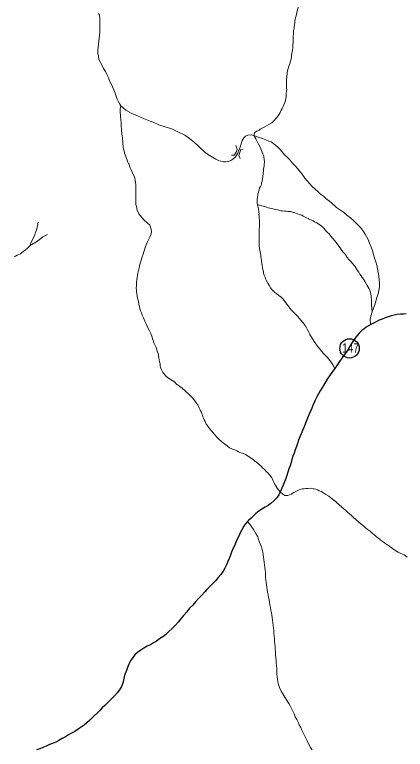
# Model space of a CAD drawing. Extents: x 781.9 to 808.1, y 7453.3 to 7481.5.
# Drawn here: x 788.63 to 791.98, y 7466.86 to 7473.15 of the extents above; entities that cross this region are included whole.
import ezdxf
from ezdxf.enums import TextEntityAlignment as Align

# ---------------------------------------------------------------- set-up
doc = ezdxf.new("R2010")
doc.units = 0
doc.header["$LTSCALE"] = 0.032
doc.linetypes.add('LONG_DASHED', pattern=[7.5, 6, -1.5])
doc.linetypes.add('MEDIUM_DASHED', pattern=[4.5, 3, -1.5])
for name, color, linetype, lineweight in [('11', 7, 'Continuous', 13), ('13', 7, 'Continuous', 25), ('4', 7, 'LONG_DASHED', 25), ('5', 7, 'LONG_DASHED', 13), ('6', 7, 'MEDIUM_DASHED', 13)]:
    doc.layers.add(name, color=color, linetype=linetype, lineweight=lineweight)
doc.layers.add('61', color=7, linetype='Continuous')

msp = doc.modelspace()

# ---------------------------------------------------------------- linework, layer by layer
at = {"layer": '11'}
for points in [[(790.5284, 7472.0312), (790.54, 7472.0008), (790.5313, 7471.9734), (790.5226, 7471.9588), (790.5132, 7471.9479), (790.4915, 7471.9494)], [(790.5636, 7471.9208), (790.5517, 7471.9443), (790.5691, 7471.9964), (790.5905, 7471.9997)]]:
    msp.add_lwpolyline(points, dxfattribs=at)
at = {"layer": '13'}
msp.add_circle((791.5019, 7470.2932), 0.083, dxfattribs=at)
msp.add_circle((791.5019, 7470.2932), 0.083, dxfattribs=at)
msp.add_circle((791.5019, 7470.2932), 0.083, dxfattribs=at)
at = {"layer": '4'}
for points in [[(791.9875, 7470.5881), (791.9632, 7470.5864), (791.9372, 7470.5848), (791.9113, 7470.5824), (791.8853, 7470.5783), (791.8594, 7470.571), (791.8334, 7470.5637), (791.8075, 7470.554), (791.7815, 7470.5443), (791.7556, 7470.5337), (791.7297, 7470.5199), (791.7025, 7470.5055), (791.6849, 7470.4975)], [(791.6849, 7470.4975), (791.6441, 7470.4735), (791.6233, 7470.4591), (791.6085, 7470.4473), (791.5845, 7470.4233), (791.5565, 7470.3897), (791.5197, 7470.3345), (791.4805, 7470.2729)], [(791.4805, 7470.2729), (791.4421, 7470.2185), (791.4045, 7470.1641), (791.3765, 7470.1217)], [(791.3765, 7470.1217), (791.3557, 7470.0945), (791.3109, 7470.0289), (791.2773, 7469.9753)], [(791.2773, 7469.9753), (791.2489, 7469.9281), (791.2351, 7469.9038), (791.2237, 7469.8835), (791.2107, 7469.8559), (791.1978, 7469.83), (791.1872, 7469.8033), (791.1775, 7469.7822), (791.1702, 7469.7611), (791.1566, 7469.7291), (791.1422, 7469.6947), (791.1254, 7469.6531), (791.1118, 7469.6203), (791.0981, 7469.5892), (791.0883, 7469.5616), (791.0762, 7469.5341), (791.0656, 7469.5065), (791.0551, 7469.4789), (791.0462, 7469.4514), (791.0364, 7469.4237), (791.0267, 7469.3962), (791.017, 7469.3687), (791.008, 7469.3411), (791.0008, 7469.3152), (790.9918, 7469.2876), (790.9829, 7469.26), (790.974, 7469.2325), (790.9643, 7469.2049), (790.9545, 7469.1773), (790.944, 7469.1498), (790.9327, 7469.1222), (790.9213, 7469.0946), (790.91, 7469.0671), (790.9081, 7469.0635)], [(790.9081, 7469.0635), (790.8954, 7469.0395), (790.8775, 7469.0119), (790.8556, 7468.9892), (790.8264, 7468.9657), (790.8037, 7468.9463), (790.7778, 7468.9325), (790.7503, 7468.9154), (790.7235, 7468.8984), (790.6999, 7468.879), (790.6781, 7468.8595), (790.6578, 7468.8401), (790.6362, 7468.8193), (790.6266, 7468.8089)], [(790.6266, 7468.8089), (790.6106, 7468.7897), (790.5954, 7468.7697), (790.5792, 7468.7395), (790.5654, 7468.7136), (790.5524, 7468.686), (790.5394, 7468.6586), (790.5273, 7468.6309), (790.5151, 7468.6033), (790.5022, 7468.5758), (790.4908, 7468.5482), (790.4803, 7468.5206), (790.4697, 7468.4931), (790.46, 7468.4671), (790.447, 7468.4395), (790.4332, 7468.412), (790.4186, 7468.3844), (790.3984, 7468.3569), (790.3773, 7468.3309), (790.3521, 7468.3025), (790.3254, 7468.2741), (790.2978, 7468.2474), (790.2792, 7468.2287), (790.2614, 7468.2076), (790.2354, 7468.1801), (790.2087, 7468.1501), (790.1827, 7468.1209), (790.1576, 7468.0933), (790.1316, 7468.0666), (790.1065, 7468.0366), (790.0797, 7468.0066), (790.0546, 7467.9742), (790.0335, 7467.9474), (790.0084, 7467.9198), (789.9857, 7467.8955), (789.9484, 7467.8615), (789.9265, 7467.8428), (789.9006, 7467.8217), (789.8746, 7467.8047), (789.8479, 7467.7852), (789.8211, 7467.7707), (789.7952, 7467.7552), (789.7676, 7467.7415), (789.74, 7467.726), (789.7125, 7467.709), (789.6849, 7467.6896), (789.6622, 7467.6677), (789.6443, 7467.6458), (789.6249, 7467.6158), (789.6119, 7467.5882)], [(789.6119, 7467.5882), (789.5998, 7467.5607), (789.59, 7467.5331), (789.5803, 7467.5072), (789.5714, 7467.4796), (789.5649, 7467.452), (789.5584, 7467.4245)], [(789.5584, 7467.4245), (789.5471, 7467.3969), (789.5308, 7467.3693), (789.5106, 7467.3418), (789.4887, 7467.3174), (789.4587, 7467.2883), (789.4319, 7467.2599), (789.4043, 7467.2339), (789.3825, 7467.2137), (789.3614, 7467.1918), (789.3419, 7467.1707), (789.3144, 7467.1463), (789.2957, 7467.1285), (789.2738, 7467.1066), (789.252, 7467.0863), (789.2268, 7467.0661), (789.2025, 7467.0474), (789.1758, 7467.0304), (789.1482, 7467.0126), (789.1206, 7466.998), (789.0931, 7466.9826), (789.0671, 7466.9672), (789.0395, 7466.951), (789.012, 7466.9355), (788.9844, 7466.921), (788.9568, 7466.9096), (788.9293, 7466.8991), (788.9017, 7466.8861), (788.8741, 7466.8747), (788.8466, 7466.8642), (788.819, 7466.8545)]]:
    msp.add_lwpolyline(points, dxfattribs=at)
at = {"layer": '5'}
for points in [[(789.3515, 7473.1611), (789.358, 7473.1475), (789.3612, 7473.1259), (789.362, 7473.0843), (789.363, 7473.0779), (789.3622, 7473.0544), (789.3614, 7473.0285), (789.3606, 7473.0025), (789.3582, 7472.9766), (789.3549, 7472.9506), (789.3525, 7472.9247), (789.35, 7472.8987), (789.3484, 7472.8728), (789.346, 7472.8469), (789.3452, 7472.8209), (789.35, 7472.795), (789.3541, 7472.7674), (789.3664, 7472.7415), (789.3809, 7472.7155), (789.3946, 7472.6896), (789.4108, 7472.6636), (789.4214, 7472.6377), (789.4352, 7472.6117), (789.4457, 7472.5858), (789.4587, 7472.5598), (789.4709, 7472.5323), (789.4822, 7472.5063), (789.4927, 7472.4804), (789.5016, 7472.4544), (789.5114, 7472.4285), (789.5227, 7472.4061), (789.5331, 7472.3845), (789.5419, 7472.3709)], [(789.5419, 7472.3709), (789.586, 7472.3341), (789.6301, 7472.3069), (789.6846, 7472.2853), (789.7375, 7472.2621), (789.766, 7472.2501), (789.7919, 7472.2396), (789.8179, 7472.2298), (789.8684, 7472.2074), (789.9301, 7472.189), (789.9589, 7472.1796), (789.9849, 7472.1699), (789.997, 7472.1658), (790.0315, 7472.1474), (790.0903, 7472.1188), (790.1179, 7472.0993), (790.1438, 7472.079), (790.173, 7472.0563), (790.2005, 7472.032), (790.2202, 7472.0124), (790.2675, 7471.9684), (790.2978, 7471.9477), (790.3562, 7471.9145), (790.3789, 7471.9023), (790.4, 7471.8966)], [(790.5183, 7471.9282), (790.5297, 7471.9429), (790.5435, 7471.9647), (790.5516, 7471.9858), (790.5524, 7471.9882), (790.5653, 7472.0162), (790.5816, 7472.075), (790.5953, 7472.0958), (790.6105, 7472.111), (790.6297, 7472.1198), (790.6578, 7472.1214), (790.6826, 7472.1158)], [(790.6826, 7472.1158), (790.7195, 7472.103), (790.7547, 7472.091), (790.7843, 7472.0806), (790.8102, 7472.0693), (790.8305, 7472.0612), (790.853, 7472.0452), (790.8874, 7472.018), (790.9107, 7471.9924), (790.9451, 7471.9516), (790.9683, 7471.9307), (790.9943, 7471.9048), (791.0105, 7471.8836), (791.038, 7471.8529), (791.0567, 7471.8342), (791.0786, 7471.8058), (791.0956, 7471.7839), (791.1199, 7471.7523), (791.137, 7471.732), (791.1621, 7471.7037), (791.1783, 7471.6834), (791.2067, 7471.6582), (791.2302, 7471.638), (791.2529, 7471.6153), (791.2772, 7471.5974), (791.2999, 7471.578), (791.3226, 7471.5594), (791.3429, 7471.544), (791.3902, 7471.5008), (791.4491, 7471.4588), (791.4791, 7471.4345), (791.5091, 7471.4102), (791.5391, 7471.3858), (791.5675, 7471.3582), (791.5956, 7471.3279), (791.6204, 7471.2943), (791.6365, 7471.2703), (791.6597, 7471.2319), (791.6718, 7471.1935), (791.6858, 7471.1588), (791.6972, 7471.128), (791.7069, 7471.0972), (791.7167, 7471.0664), (791.7264, 7471.0356), (791.7353, 7471.0048), (791.7418, 7470.974), (791.7483, 7470.9432), (791.7531, 7470.9124), (791.7564, 7470.8816), (791.7572, 7470.8508), (791.7572, 7470.82), (791.7539, 7470.7891), (791.7459, 7470.76), (791.7369, 7470.7291), (791.728, 7470.6983), (791.7183, 7470.6675), (791.7077, 7470.6383), (791.6964, 7470.6075)], [(790.4, 7471.8966), (790.4211, 7471.8918), (790.4422, 7471.8902), (790.4632, 7471.8942), (790.4843, 7471.9023), (790.5029, 7471.9145), (790.5183, 7471.9282)], [(791.6964, 7470.6075), (791.6859, 7470.5767), (791.6794, 7470.5459), (791.6786, 7470.5251), (791.6849, 7470.4975)], [(790.6266, 7468.8089), (790.6434, 7468.7911), (790.6594, 7468.7695), (790.6797, 7468.742), (790.691, 7468.7217), (790.7016, 7468.7006), (790.7147, 7468.6779), (790.7227, 7468.6552), (790.7308, 7468.6341), (790.7389, 7468.6131), (790.7462, 7468.592), (790.7519, 7468.5709), (790.7592, 7468.5482), (790.7616, 7468.5255), (790.7648, 7468.5044), (790.7673, 7468.4833), (790.7705, 7468.4622), (790.7721, 7468.4396), (790.7754, 7468.4168), (790.7778, 7468.3958), (790.7802, 7468.3747), (790.7819, 7468.3536), (790.7827, 7468.3325), (790.7859, 7468.3098), (790.7883, 7468.2887), (790.79, 7468.2677), (790.7924, 7468.2466), (790.7948, 7468.2255), (790.7997, 7468.2044), (790.8046, 7468.1817), (790.8078, 7468.1606), (790.8119, 7468.1396), (790.8167, 7468.1185), (790.8191, 7468.0974), (790.824, 7468.0747), (790.8281, 7468.052), (790.8322, 7468.0279), (790.8394, 7467.9879), (790.8419, 7467.9661), (790.8435, 7467.9434), (790.8467, 7467.9207), (790.8492, 7467.898), (790.8516, 7467.8736), (790.854, 7467.8509), (790.8564, 7467.8282), (790.8581, 7467.8055), (790.8597, 7467.7828), (790.8621, 7467.7585), (790.8646, 7467.7358), (790.8654, 7467.7131), (790.867, 7467.6904), (790.8686, 7467.6677), (790.8702, 7467.6434), (790.8719, 7467.6191), (790.8727, 7467.5964), (790.8751, 7467.5737), (790.8775, 7467.551), (790.8783, 7467.5266), (790.8791, 7467.5039), (790.8808, 7467.4812), (790.8832, 7467.4585), (790.8873, 7467.4358), (790.8929, 7467.4131), (790.9017, 7467.3888), (790.9172, 7467.3572), (790.931, 7467.3353), (790.9481, 7467.3061), (790.9626, 7467.2834), (790.9813, 7467.2526), (790.9943, 7467.2315), (791.0048, 7467.2088), (791.0162, 7467.1861), (791.0283, 7467.1618), (791.0372, 7467.1375), (791.0494, 7467.1148), (791.0608, 7467.0921), (791.0713, 7467.0694), (791.0835, 7467.045), (791.0932, 7467.0223), (791.1037, 7466.9996), (791.1159, 7466.9769), (791.1264, 7466.9542), (791.1386, 7466.9315), (791.1507, 7466.9072), (791.1686, 7466.8756), (791.1824, 7466.8537)]]:
    msp.add_lwpolyline(points, dxfattribs=at)
at = {"layer": '6'}
for points in [[(791.0665, 7473.2336), (791.0583, 7473.2052), (791.0534, 7473.1841), (791.0494, 7473.1695), (791.0461, 7473.1549), (791.0437, 7473.1404), (791.0388, 7473.1258)], [(791.0388, 7473.1258), (791.0372, 7473.1112), (791.034, 7473.0966), (791.0324, 7473.082), (791.0308, 7473.0682), (791.0267, 7473.035), (791.0226, 7473.0123), (791.0226, 7472.9977), (791.0202, 7472.9831), (791.0194, 7472.9685), (791.0194, 7472.9539), (791.0186, 7472.9393), (791.0178, 7472.9247), (791.0178, 7472.9101), (791.017, 7472.8963), (791.0145, 7472.8712), (791.0121, 7472.8485), (791.0097, 7472.8339), (791.0072, 7472.8193), (791.0056, 7472.8047), (791.0032, 7472.7901), (791.0007, 7472.7755), (790.9975, 7472.7609), (790.9941, 7472.7463), (790.9919, 7472.739), (790.9821, 7472.7107), (790.9756, 7472.6904), (790.9699, 7472.6717), (790.9683, 7472.6571), (790.9659, 7472.6425), (790.9643, 7472.628), (790.9634, 7472.6134), (790.9626, 7472.5988), (790.9627, 7472.5931), (790.961, 7472.5631), (790.9626, 7472.5404), (790.9626, 7472.5258), (790.9634, 7472.5112), (790.961, 7472.495), (790.9594, 7472.4804), (790.9594, 7472.4658), (790.9594, 7472.4496), (790.9594, 7472.4488), (790.9529, 7472.4204), (790.9464, 7472.3985), (790.9399, 7472.3782), (790.9326, 7472.3636), (790.9245, 7472.349), (790.9164, 7472.3328), (790.9091, 7472.3182), (790.9059, 7472.3126), (790.8897, 7472.2842), (790.8726, 7472.2639), (790.8597, 7472.2485), (790.8368, 7472.2264), (790.8103, 7472.2112), (790.7698, 7472.1883), (790.747, 7472.1755), (790.7373, 7472.1698), (790.7275, 7472.1633), (790.7178, 7472.1593), (790.7065, 7472.1536), (790.6967, 7472.1463), (790.6886, 7472.1391), (790.6886, 7472.1358), (790.6826, 7472.1158)], [(789.5419, 7472.3709), (789.5368, 7472.3455), (789.536, 7472.3198), (789.538, 7472.2849), (789.5389, 7472.2761), (789.5406, 7472.2534), (789.5438, 7472.2249), (789.5438, 7472.2193), (789.5454, 7472.2047), (789.5454, 7472.1901), (789.5478, 7472.1739), (789.5478, 7472.1577), (789.5503, 7472.1415), (789.5519, 7472.1269), (789.5535, 7472.1123), (789.5558, 7472.0956), (789.5602, 7472.0559), (789.5618, 7472.0102), (789.5694, 7471.9865), (789.5738, 7471.9647), (789.5835, 7471.9356), (789.5973, 7471.9039), (789.603, 7471.8885), (789.607, 7471.8772), (789.6127, 7471.8707), (789.616, 7471.8529), (789.6249, 7471.835), (789.6322, 7471.8172), (789.6452, 7471.7888), (789.6607, 7471.7564), (789.6614, 7471.7507), (789.6646, 7471.7329), (789.667, 7471.715), (789.6695, 7471.6972), (789.6703, 7471.6777), (789.6703, 7471.6583), (789.6695, 7471.6307), (789.6703, 7471.5958), (789.6695, 7471.5821), (789.6703, 7471.5626), (789.6695, 7471.5432), (789.6719, 7471.5253), (789.6768, 7471.5075), (789.6824, 7471.4783), (789.6954, 7471.445), (789.7076, 7471.4304), (789.7238, 7471.4101), (789.7417, 7471.3915), (789.7668, 7471.368), (789.7895, 7471.3477), (789.796, 7471.3324), (789.8032, 7471.3129), (789.804, 7471.2934), (789.8024, 7471.274), (789.7911, 7471.2448), (789.7757, 7471.2164), (789.7684, 7471.1993), (789.7603, 7471.1799), (789.7514, 7471.1564), (789.7416, 7471.1297), (789.7295, 7471.0915), (789.7278, 7471.0859), (789.723, 7471.068), (789.7165, 7471.0486), (789.7116, 7471.0291), (789.706, 7471.0113), (789.6986, 7470.9821), (789.6898, 7470.9489), (789.6873, 7470.9367), (789.6849, 7470.9172), (789.6808, 7470.8994), (789.6784, 7470.8816), (789.6759, 7470.8637), (789.6751, 7470.8345), (789.6744, 7470.8029), (789.6751, 7470.7972), (789.6768, 7470.7794), (789.68, 7470.7616), (789.6833, 7470.7437), (789.6849, 7470.7243), (789.6938, 7470.6951), (789.6971, 7470.6683), (789.7011, 7470.6513), (789.7043, 7470.6335), (789.71, 7470.6156), (789.7181, 7470.5962), (789.7254, 7470.5767), (789.7368, 7470.5556), (789.7481, 7470.5273), (789.7514, 7470.52), (789.7587, 7470.5021), (789.7684, 7470.4827), (789.7765, 7470.4632), (789.7862, 7470.4429), (789.7984, 7470.4194)], [(790.6826, 7472.1158), (790.6986, 7472.0873), (790.7195, 7472.048), (790.7351, 7472.0171), (790.7544, 7471.973), (790.766, 7471.9389), (790.7709, 7471.9052), (790.7713, 7471.904), (790.7729, 7471.8958), (790.7721, 7471.8885), (790.7705, 7471.8723), (790.7689, 7471.8561), (790.7681, 7471.8415), (790.7656, 7471.8269), (790.7648, 7471.8123), (790.7624, 7471.7976), (790.7616, 7471.7937), (790.7575, 7471.7621), (790.7551, 7471.7394), (790.7535, 7471.7248), (790.7486, 7471.7102), (790.7462, 7471.6956), (790.7381, 7471.681), (790.7316, 7471.6664), (790.7275, 7471.6518), (790.7243, 7471.6429), (790.717, 7471.608), (790.7137, 7471.5853), (790.7105, 7471.5707), (790.7097, 7471.5561)], [(790.7097, 7471.5561), (790.7101, 7471.5405), (790.7141, 7471.526)], [(790.7141, 7471.526), (790.7221, 7471.4867), (790.7265, 7471.4422), (790.7259, 7471.441), (790.7267, 7471.4248)], [(790.7141, 7471.526), (790.7315, 7471.5207), (790.7624, 7471.5107), (790.773, 7471.5074), (790.7892, 7471.5026), (790.8054, 7471.4977), (790.82, 7471.4953), (790.8347, 7471.492), (790.8573, 7471.4864), (790.8856, 7471.4799), (790.8962, 7471.4774), (790.9124, 7471.4726), (790.9286, 7471.4701), (790.9432, 7471.4685), (790.9578, 7471.4677), (790.9724, 7471.4669), (790.9951, 7471.4653), (791.0202, 7471.4572), (791.0259, 7471.4556), (791.0421, 7471.4499), (791.0567, 7471.4458), (791.0713, 7471.441), (791.0916, 7471.4329), (791.1054, 7471.4264), (791.1281, 7471.415), (791.1516, 7471.4021), (791.154, 7471.4012), (791.1702, 7471.3948), (791.1897, 7471.3842), (791.2027, 7471.3761), (791.2205, 7471.3672), (791.2318, 7471.3591), (791.2545, 7471.3445), (791.2748, 7471.3299), (791.2845, 7471.3193), (791.2967, 7471.304), (791.3137, 7471.2861), (791.3259, 7471.274), (791.3405, 7471.2545), (791.3583, 7471.2334), (791.3753, 7471.2132), (791.3842, 7471.2034), (791.3956, 7471.1897), (791.4086, 7471.1694), (791.4207, 7471.1556), (791.4305, 7471.141), (791.445, 7471.1199), (791.4686, 7471.0932), (791.471, 7471.0891), (791.4807, 7471.0729), (791.4969, 7471.0534), (791.514, 7471.0364), (791.5302, 7471.0186), (791.5464, 7470.9959), (791.561, 7470.9748), (791.5707, 7470.9602), (791.5813, 7470.9447), (791.5894, 7470.9302), (791.6007, 7470.9156), (791.6113, 7470.901), (791.621, 7470.8864), (791.6348, 7470.8629), (791.651, 7470.8386), (791.6542, 7470.8329), (791.6623, 7470.8167), (791.6688, 7470.8021), (791.6753, 7470.7931), (791.6769, 7470.7875), (791.681, 7470.7729), (791.6834, 7470.7583), (791.6858, 7470.7421), (791.6875, 7470.7259), (791.6898, 7470.7156), (791.691, 7470.6871), (791.691, 7470.6655), (791.6922, 7470.6354), (791.6964, 7470.6075)], [(790.7267, 7471.4248), (790.7283, 7471.4086), (790.7299, 7471.3923), (790.7316, 7471.3778), (790.7299, 7471.3632), (790.7299, 7471.3486), (790.7292, 7471.338), (790.7283, 7471.308), (790.7275, 7471.2837), (790.7275, 7471.2675), (790.7267, 7471.2529), (790.7267, 7471.2383), (790.7267, 7471.2237), (790.7275, 7471.2091), (790.7276, 7471.2067), (790.7283, 7471.1734), (790.7316, 7471.1491), (790.7341, 7471.1345), (790.7356, 7471.1199), (790.7389, 7471.1053), (790.7405, 7471.0907), (790.7429, 7471.0762), (790.7445, 7471.0616), (790.7478, 7471.0453), (790.7486, 7471.0364), (790.7535, 7471.0048), (790.7567, 7470.9821), (790.7599, 7470.9675), (790.7632, 7470.9529), (790.7656, 7470.9367), (790.7713, 7470.9205), (790.7778, 7470.9043), (790.7826, 7470.8897), (790.7875, 7470.8775), (790.8021, 7470.8515), (790.8151, 7470.8281), (790.8248, 7470.8118), (790.8353, 7470.7988), (790.8516, 7470.781), (790.8621, 7470.7713), (790.8792, 7470.7607), (790.897, 7470.747), (790.9172, 7470.7324), (790.9254, 7470.7235), (790.9343, 7470.7137), (790.9481, 7470.6951), (790.9578, 7470.6805), (790.974, 7470.661), (790.9837, 7470.6472), (790.9878, 7470.6408), (791.0072, 7470.6188), (791.0259, 7470.5978), (791.0445, 7470.5807), (791.0575, 7470.5661), (791.0721, 7470.5492), (791.0818, 7470.5378), (791.1037, 7470.511), (791.1207, 7470.4883), (791.1337, 7470.4681), (791.1426, 7470.4527), (791.1516, 7470.4324), (791.1613, 7470.4162), (791.1629, 7470.4121), (791.1767, 7470.3886), (791.1897, 7470.3658), (791.1994, 7470.3529), (791.2124, 7470.3335), (791.2221, 7470.3197), (791.2367, 7470.3011), (791.2432, 7470.2921), (791.2626, 7470.2702), (791.2797, 7470.2492), (791.2975, 7470.2305), (791.3145, 7470.2111), (791.3307, 7470.1908), (791.3348, 7470.1851), (791.3593, 7470.1526), (791.3765, 7470.1217)], [(788.8343, 7471.3751), (788.8283, 7471.3434), (788.8255, 7471.3307), (788.8214, 7471.3161), (788.8157, 7471.2999), (788.8101, 7471.2837), (788.8076, 7471.2764), (788.806, 7471.2723), (788.8044, 7471.2683), (788.8038, 7471.267), (788.7938, 7471.2409), (788.7721, 7471.196), (788.7641, 7471.1736)], [(788.7641, 7471.1736), (788.8272, 7471.2124), (788.8727, 7471.2473), (788.9133, 7471.2697)], [(788.7641, 7471.1736), (788.7428, 7471.1514), (788.7233, 7471.1345), (788.6982, 7471.1159), (788.6941, 7471.1134), (788.6812, 7471.1037), (788.6682, 7471.0972), (788.6544, 7471.0907), (788.6405, 7471.0842), (788.6277, 7471.0802)], [(789.7984, 7470.4194), (789.8098, 7470.3894), (789.8146, 7470.374), (789.8219, 7470.3546), (789.8276, 7470.3351), (789.8357, 7470.3173), (789.8446, 7470.2994)], [(789.8446, 7470.2994), (789.8535, 7470.2703), (789.8649, 7470.2402), (789.8649, 7470.233), (789.8673, 7470.2135), (789.8697, 7470.1957), (789.873, 7470.1778), (789.8786, 7470.16), (789.8803, 7470.1422), (789.8876, 7470.1146), (789.9014, 7470.0854), (789.9119, 7470.074), (789.9281, 7470.0554), (789.9354, 7470.0489), (789.946, 7470.0408), (789.9467, 7470.0409), (789.968, 7470.0253), (790.0017, 7470.0053), (790.023, 7469.984), (790.0287, 7469.98), (790.0408, 7469.9735), (790.0514, 7469.9637), (790.0635, 7469.954), (790.0765, 7469.9451), (790.0878, 7469.9354), (790.1024, 7469.9201), (790.126, 7469.9013), (790.1308, 7469.8956), (790.1413, 7469.8835), (790.1559, 7469.8697), (790.1689, 7469.8551), (790.177, 7469.8438), (790.1867, 7469.8276), (790.2005, 7469.8089), (790.2135, 7469.7846), (790.2192, 7469.7724), (790.2257, 7469.7595), (790.2322, 7469.7465), (790.237, 7469.7335), (790.2411, 7469.7206), (790.2451, 7469.7076), (790.25, 7469.6946), (790.2573, 7469.6808), (790.2638, 7469.667), (790.2727, 7469.6451), (790.2816, 7469.6346), (790.2946, 7469.6184), (790.3027, 7469.607), (790.3132, 7469.5932), (790.3222, 7469.5843), (790.3327, 7469.5689), (790.3473, 7469.5527), (790.3684, 7469.5292), (790.3764, 7469.5211), (790.387, 7469.5105), (790.3992, 7469.5008), (790.4113, 7469.4911), (790.4227, 7469.4813), (790.4324, 7469.4724), (790.4527, 7469.4587), (790.4722, 7469.4425), (790.4932, 7469.4335), (790.5054, 7469.4278), (790.5184, 7469.423), (790.5346, 7469.4157), (790.55, 7469.4084), (790.5622, 7469.4027), (790.5824, 7469.3954), (790.6051, 7469.3857), (790.6092, 7469.3832), (790.6246, 7469.3743), (790.6351, 7469.367), (790.6497, 7469.3589), (790.6627, 7469.35), (790.6748, 7469.3403), (790.687, 7469.3306), (790.7049, 7469.3184), (790.7276, 7469.2998), (790.7316, 7469.2957), (790.7453, 7469.2835), (790.7567, 7469.2713), (790.7672, 7469.26), (790.7786, 7469.2503), (790.7883, 7469.2397), (790.8021, 7469.2268), (790.8159, 7469.209), (790.8346, 7469.183), (790.8402, 7469.1725), (790.8459, 7469.1595), (790.8524, 7469.1465), (790.8597, 7469.1336), (790.867, 7469.1206), (790.8751, 7469.1068), (790.875, 7469.1052), (790.8906, 7469.0831)], [(790.8906, 7469.0831), (790.9067, 7469.0647), (790.9081, 7469.0635)], [(790.9081, 7469.0635), (790.9324, 7469.043), (790.9432, 7469.0362), (790.948, 7469.033), (790.9578, 7469.0322), (790.9675, 7469.033)], [(790.9675, 7469.033), (790.9724, 7469.033), (790.987, 7469.0387), (791.0016, 7469.0452), (791.0243, 7469.0581), (791.0527, 7469.0736), (791.0534, 7469.0735), (791.0697, 7469.0816), (791.0843, 7469.0865), (791.0989, 7469.0897), (791.1135, 7469.0914), (791.1281, 7469.093), (791.1443, 7469.0938), (791.1686, 7469.0946), (791.1937, 7469.0906), (791.1978, 7469.0897), (791.2124, 7469.0865), (791.227, 7469.0808), (791.2416, 7469.0744), (791.2602, 7469.0662), (791.274, 7469.0589), (791.2983, 7469.0427), (791.3251, 7469.0265), (791.3372, 7469.0168), (791.3534, 7469.0038), (791.3705, 7468.9916), (791.3737, 7468.9892), (791.3761, 7468.9868), (791.3842, 7468.9795), (791.3858, 7468.9778), (791.3891, 7468.9754), (791.3907, 7468.9738), (791.4013, 7468.9641), (791.4167, 7468.9503), (791.4321, 7468.9365), (791.4515, 7468.9195), (791.4718, 7468.9008), (791.4872, 7468.8887), (791.5026, 7468.8757), (791.5172, 7468.8619), (791.5326, 7468.8482), (791.6015, 7468.7881), (791.6242, 7468.7703), (791.6396, 7468.7573), (791.6526, 7468.7452), (791.6778, 7468.7265), (791.6988, 7468.7087), (791.715, 7468.6949), (791.7313, 7468.6828), (791.7434, 7468.6706), (791.7604, 7468.6584), (791.7645, 7468.6544), (791.7904, 7468.6365), (791.814, 7468.6203), (791.8286, 7468.609), (791.8432, 7468.5992), (791.8578, 7468.5887), (791.8707, 7468.5782), (791.8894, 7468.5636), (791.9178, 7468.5474), (791.9405, 7468.5352), (791.955, 7468.5295), (791.9696, 7468.5238), (791.9965, 7468.5058)]]:
    msp.add_lwpolyline(points, dxfattribs=at)

# ---------------------------------------------------------------- texts
at = {"layer": '61', "width": 0.8}
msp.add_text('147', height=0.08, dxfattribs=at).set_placement((791.5106, 7470.2574), align=Align.CENTER)

doc.saveas('drawing.dxf')
